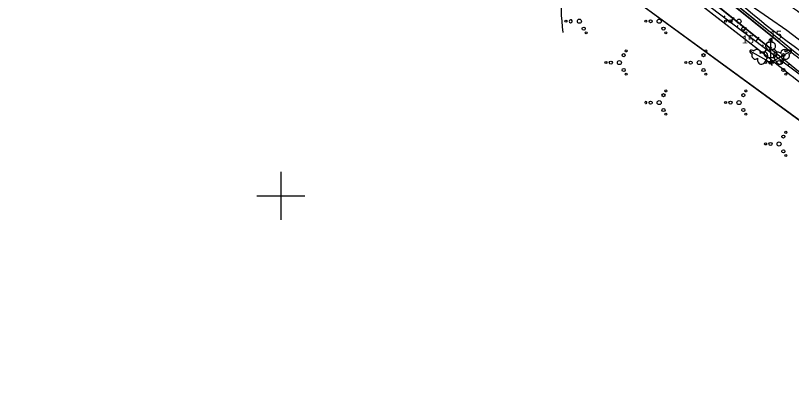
# Model space of a CAD drawing. Extents: x 514086 to 514457, y 297399 to 297567.
# Drawn here: x 514133.42 to 514181.92, y 297438.52 to 297461.26 of the extents above; entities that cross this region are included whole.
import ezdxf

# ---------------------------------------------------------------- set-up
doc = ezdxf.new("R2010")
doc.units = 0
for name, color, linetype in [('AA_Brauktuve', 7, 'Continuous'), ('AA_cela_mala', 7, 'Continuous'), ('AA_nogaze', 7, 'Continuous'), ('AA_Nomale', 7, 'Continuous'), ('AA_Zale', 7, 'Continuous'), ('Level 1', 7, 'Continuous'), ('Level 21', 7, 'Continuous'), ('Level 23', 7, 'Continuous'), ('Level 29', 7, 'Continuous'), ('Level 30', 7, 'Continuous'), ('Level 37', 7, 'Continuous'), ('Level 45', 7, 'Continuous'), ('Level 46', 7, 'Continuous')]:
    doc.layers.add(name, color=color, linetype=linetype)

msp = doc.modelspace()

# ---------------------------------------------------------------- linework, layer by layer
at = {"layer": 'AA_Brauktuve'}
msp.add_lwpolyline([(514139.852, 297493.058), (514181.234, 297459.714)], dxfattribs=at)
msp.add_arc((514308.288, 297617.396), 202.5, 231.13942, 232.4775, dxfattribs=at)
at = {"layer": 'AA_cela_mala'}
for p, q in [((514139.758, 297492.942), (514181.14, 297459.597)), ((514139.852, 297493.058), (514181.234, 297459.714))]:
    msp.add_line(p, q, dxfattribs=at)
for radius in [202.65, 202.5]:
    msp.add_arc((514308.288, 297617.396), radius, 231.13942, 232.4775, dxfattribs=at)
at = {"layer": 'AA_nogaze'}
for p, q in [((514177.715, 297461.165), (514177.781, 297461.252)), ((514178.114, 297460.864), (514178.326, 297461.145)), ((514178.514, 297460.563), (514178.575, 297460.644)), ((514178.913, 297460.262), (514179.11, 297460.524)), ((514179.312, 297459.961), (514179.369, 297460.037)), ((514179.711, 297459.66), (514179.895, 297459.903)), ((514180.111, 297459.359), (514180.163, 297459.429)), ((514180.51, 297459.058), (514180.679, 297459.282)), ((514180.909, 297458.757), (514180.958, 297458.821)), ((514181.308, 297458.456), (514181.464, 297458.662)), ((514181.707, 297458.155), (514181.752, 297458.214))]:
    msp.add_line(p, q, dxfattribs=at)
msp.add_lwpolyline([(514139.381, 297492.411), (514153.448, 297479.653), (514157.356, 297476.515), (514190.113, 297451.817)], dxfattribs=at)
at = {"layer": 'AA_Nomale'}
for points in [[(514181.14, 297459.597), (514139.77, 297492.933)], [(514139.413, 297492.389), (514139.411, 297492.386), (514180.732, 297459.091)]]:
    msp.add_lwpolyline(points, dxfattribs=at)
for radius in [202.65, 203.3]:
    msp.add_arc((514308.288, 297617.396), radius, 231.13942, 232.4775, dxfattribs=at)
at = {"layer": 'AA_Zale'}
msp.add_line((514139.35, 297492.435), (514180.732, 297459.091), dxfattribs=at)
for points in [[(514180.732, 297459.091), (514139.411, 297492.386), (514139.381, 297492.411)], [(514139.036, 297492.046), (514153.448, 297479.653), (514180.419, 297458.702)], [(514139.139, 297491.971), (514139.135, 297491.966), (514153.455, 297479.647), (514180.419, 297458.702)]]:
    msp.add_lwpolyline(points, dxfattribs=at)
for radius in [203.3, 203.3, 203.8, 203.8]:
    msp.add_arc((514308.288, 297617.396), radius, 231.13942, 232.4775, dxfattribs=at)
at = {"layer": 'Level 1'}
for p, q in [((514180.311, 297458.489), (514180.612, 297458.316)), ((514180.612, 297458.663), (514180.612, 297458.316)), ((514180.612, 297458.316), (514180.712, 297458.489)), ((514180.913, 297458.489), (514180.612, 297458.316)), ((514180.612, 297458.316), (514180.812, 297458.316)), ((514180.612, 297458.316), (514180.712, 297458.143))]:
    msp.add_line(p, q, dxfattribs=at)
for points in [[(514180.612, 297459.816), (514180.612, 297458.663)], [(514180.702, 297459.584), (514180.701, 297459.585)], [(514179.313, 297459.066), (514180.311, 297458.489)], [(514179.559, 297459.027), (514179.558, 297459.027)], [(514181.911, 297459.066), (514180.913, 297458.489)], [(514181.755, 297458.872), (514181.755, 297458.874)]]:
    msp.add_lwpolyline(points, dxfattribs=at)
for centre, major_axis, ratio, start_param, end_param in [((514180.484, 297459.371), (-0.039, -0.212), 0.861323, 3.141593, 6.283185), ((514180.612, 297459.666), (0, -0.15), 0.707107, 3.14537, 5.287485), ((514180.612, 297459.666), (0, -0.15), 0.707107, 0.995701, 3.137816), ((514180.74, 297459.371), (0.039, -0.212), 0.861323, 0, 3.141593), ((514179.443, 297458.991), (0.13, -0.075), 0.707107, 3.14537, 5.287485), ((514179.443, 297458.991), (0.13, -0.075), 0.707107, 0.995701, 3.137816), ((514179.634, 297458.732), (0.165, -0.14), 0.861323, 3.141593, 6.283185), ((514179.762, 297458.955), (0.203, -0.073), 0.861323, 0, 3.141593), ((514180.143, 297458.69), (-0.236, -0.218), 0.814445, 1.531171, 4.712389), ((514180.522, 297458.909), (0.307, 0.095), 0.814445, 1.570796, 4.752015), ((514180.702, 297458.909), (-0.307, 0.095), 0.814445, 1.531171, 4.712389), ((514181.081, 297458.69), (0.236, -0.218), 0.814445, 1.570796, 4.752015), ((514181.462, 297458.955), (-0.203, -0.073), 0.861323, 3.141593, 6.283185), ((514181.59, 297458.732), (-0.165, -0.14), 0.861323, 0, 3.141593), ((514181.781, 297458.991), (-0.13, -0.075), 0.707107, 3.14537, 5.287485), ((514181.781, 297458.991), (-0.13, -0.075), 0.707107, 0.995701, 3.137816), ((514180.054, 297458.535), (0.071, 0.313), 0.814445, 1.570796, 4.752015), ((514181.17, 297458.535), (-0.071, 0.313), 0.814445, 1.531171, 4.712389)]:
    msp.add_ellipse(centre, major_axis=major_axis, ratio=ratio, start_param=start_param, end_param=end_param, dxfattribs=at)
at = {"layer": 'Level 21'}
msp.add_spline([(514167.656, 297460.196), (514167.656, 297463.017), (514169.677, 297465.792), (514173.482, 297465.792), (514178.65, 297462.077), (514185.698, 297456.857), (514187.671, 297455.211), (514188.469, 297452.531), (514186.966, 297450.274), (514184.429, 297447.265)], degree=3, dxfattribs=at)
at = {"layer": 'Level 23'}
for centre, radius in [((514167.823, 297460.908), 0.064), ((514168.662, 297460.908), 0.128), ((514172.812, 297460.908), 0.064), ((514173.115, 297460.908), 0.096), ((514173.651, 297460.908), 0.128), ((514177.801, 297460.908), 0.064), ((514178.104, 297460.908), 0.096), ((514178.64, 297460.908), 0.128), ((514168.93, 297460.444), 0.096), ((514173.919, 297460.444), 0.096), ((514178.908, 297460.444), 0.096), ((514169.082, 297460.181), 0.064), ((514174.071, 297460.181), 0.064), ((514179.06, 297460.181), 0.064), ((514171.43, 297458.787), 0.096), ((514171.582, 297459.05), 0.064), ((514176.419, 297458.787), 0.096), ((514176.571, 297459.05), 0.064), ((514181.408, 297458.787), 0.096), ((514181.56, 297459.05), 0.064), ((514170.323, 297458.323), 0.064), ((514170.626, 297458.323), 0.096), ((514171.162, 297458.323), 0.128), ((514175.312, 297458.323), 0.064), ((514175.615, 297458.323), 0.096), ((514176.151, 297458.323), 0.128), ((514180.301, 297458.323), 0.064), ((514180.604, 297458.323), 0.096), ((514181.14, 297458.323), 0.128), ((514171.43, 297457.859), 0.096), ((514176.419, 297457.859), 0.096), ((514181.408, 297457.859), 0.096), ((514171.582, 297457.596), 0.064), ((514176.571, 297457.596), 0.064), ((514181.56, 297457.596), 0.064), ((514174.071, 297456.55), 0.064), ((514179.06, 297456.55), 0.064), ((514173.919, 297456.287), 0.096), ((514178.908, 297456.287), 0.096), ((514173.115, 297455.823), 0.096), ((514173.651, 297455.823), 0.128), ((514177.801, 297455.823), 0.064), ((514178.104, 297455.823), 0.096), ((514178.64, 297455.823), 0.128), ((514173.919, 297455.359), 0.096), ((514174.071, 297455.096), 0.064), ((514178.908, 297455.359), 0.096), ((514179.06, 297455.096), 0.064), ((514181.56, 297453.965), 0.064), ((514181.408, 297453.702), 0.096), ((514180.301, 297453.238), 0.064), ((514180.604, 297453.238), 0.096), ((514181.14, 297453.238), 0.128), ((514181.408, 297452.774), 0.096), ((514181.56, 297452.511), 0.064)]:
    msp.add_circle(centre, radius, dxfattribs=at)
for centre, radius, start, end in [((514168.126, 297460.908), 0.096, 98.6542, 217.7771), ((514168.126, 297460.908), 0.096, 217.7771, 98.6542), ((514172.812, 297455.823), 0.064, 258.281, 212.8559)]:
    msp.add_arc(centre, radius, start, end, dxfattribs=at)
at = {"layer": 'Level 29'}
msp.add_line((514139.134, 297486.37), (514229.261, 297420.493), dxfattribs=at)
at = {"layer": 'Level 30'}
for p, q in [((514150, 297451.5), (514150, 297450)), ((514148.5, 297450), (514150, 297450)), ((514150, 297450), (514150, 297448.5)), ((514150, 297450), (514151.5, 297450))]:
    msp.add_line(p, q, dxfattribs=at)
at = {"layer": 'Level 37'}
for points in [[(514139.874, 297497.035), (514148.452, 297493.087), (514152.9, 297490.654), (514155.012, 297489.24), (514157.055, 297487.727), (514160.163, 297485.252), (514163.225, 297482.729), (514166.288, 297480.21), (514169.399, 297477.75), (514184.679, 297466.049), (514188.685, 297462.979), (514190.692, 297461.445), (514192.708, 297459.912), (514193.134, 297459.688), (514193.613, 297459.574), (514194.114, 297459.524), (514194.606, 297459.489), (514195.045, 297459.442), (514195.506, 297459.417), (514195.979, 297459.548), (514196.259, 297459.707)], [(514136.849, 297494.086), (514140.775, 297492.444), (514142.699, 297491.153), (514143.967, 297490.173), (514145.225, 297489.179), (514146.485, 297488.19), (514147.764, 297487.226), (514149.635, 297485.885), (514151.52, 297484.563), (514153.402, 297483.236), (514155.263, 297481.88), (514159.161, 297478.934), (514163.043, 297475.965), (514166.923, 297472.996), (514170.82, 297470.048), (514173.26, 297468.237), (514175.709, 297466.438), (514178.159, 297464.639), (514180.6, 297462.828), (514184.429, 297459.874), (514186.323, 297458.371), (514188.215, 297456.863), (514189.034, 297456.154), (514191.11, 297453.709)]]:
    msp.add_spline(points, degree=3, dxfattribs=at)
at = {"layer": 'Level 45'}
msp.add_lwpolyline([(514165.491, 297472.425), (514167.329, 297470.46), (514170.146, 297468.31), (514175.888, 297464.328), (514181.629, 297460.345), (514185.517, 297457.375), (514189.404, 297454.406)], dxfattribs=at)
at = {"layer": 'Level 46'}
msp.add_lwpolyline([(514139.134, 297486.37), (514229.261, 297420.493), (514237.863, 297414.208), (514250.009, 297428.181), (514295.433, 297494.723), (514312.775, 297524.542), (514316.491, 297528.738), (514320.446, 297531.016), (514328.236, 297532.215), (514332.539, 297530.572), (514332.631, 297530.536), (514341.642, 297542.18), (514320.211, 297553.997), (514285.885, 297496.27), (514243.195, 297433.696), (514241.534, 297432.407), (514239.451, 297432.203), (514209.969, 297445.237), (514194.45, 297457.413), (514175.859, 297473.677), (514139.316, 297503.122), (514133.046, 297508.174), (514130.604, 297489.221)], close=True, dxfattribs=at)

# ---------------------------------------------------------------- texts
at = {"layer": 'Level 1'}
for p in [(514178.638, 297459.516), (514180.387, 297459.816)]:
    msp.add_text(' 15', height=0.5, dxfattribs=at).set_placement(p)

doc.saveas('drawing.dxf')
